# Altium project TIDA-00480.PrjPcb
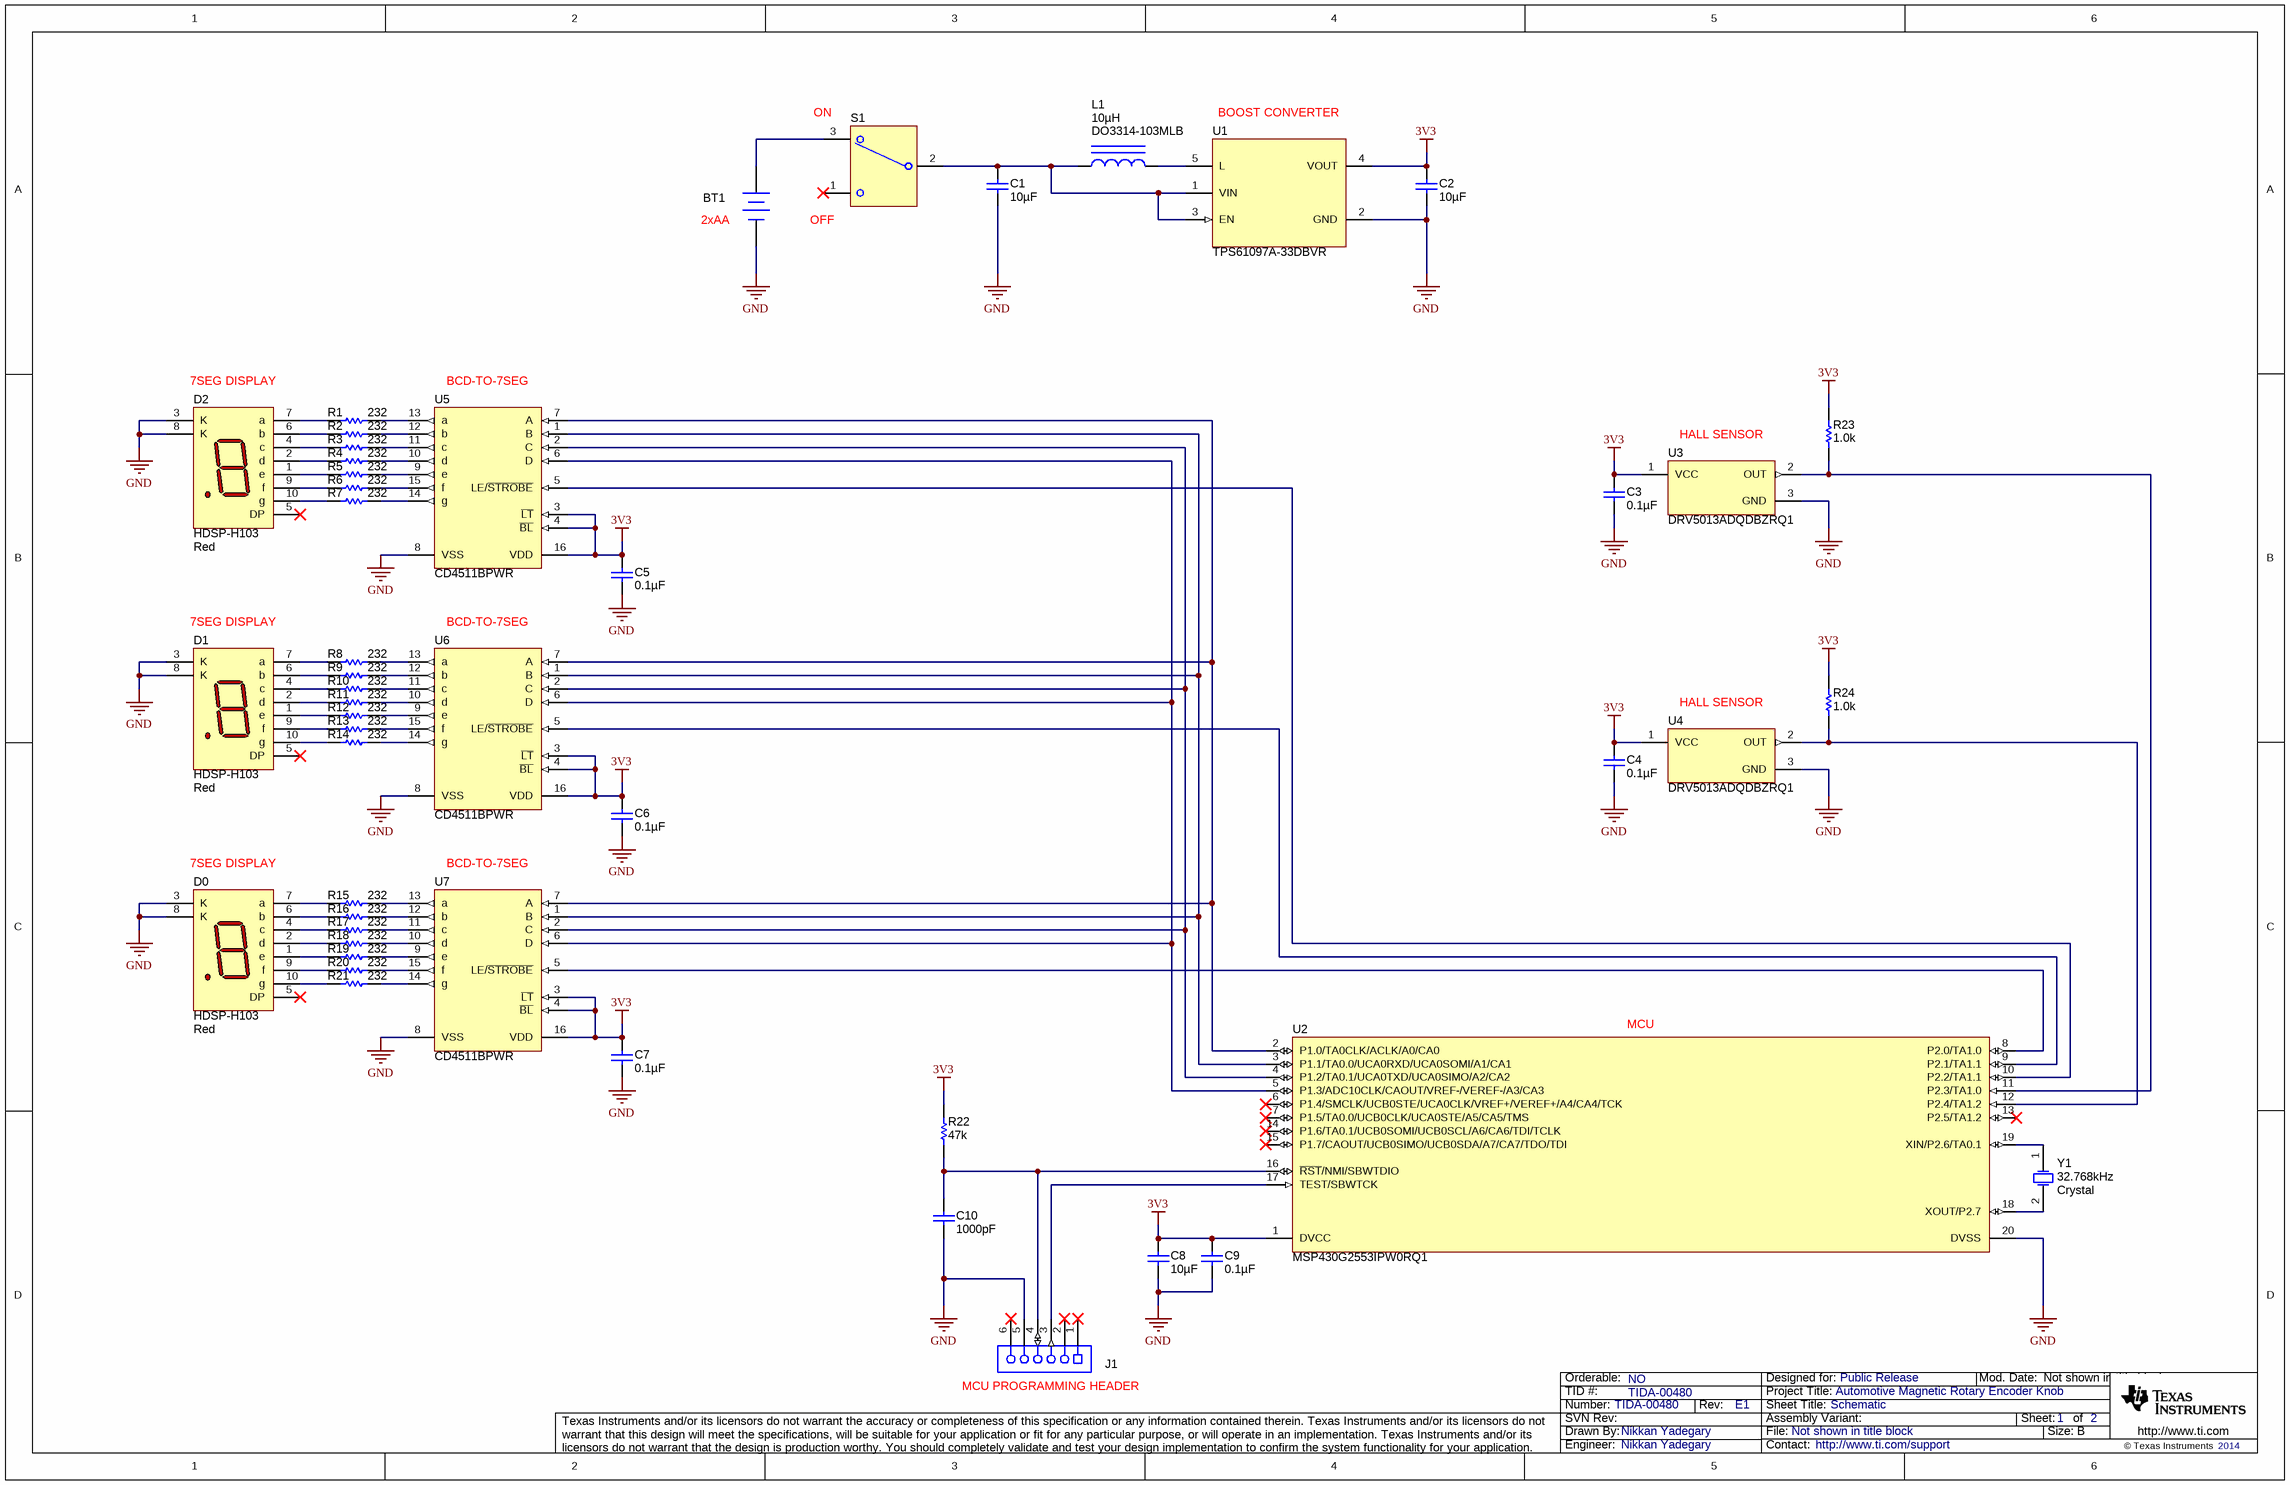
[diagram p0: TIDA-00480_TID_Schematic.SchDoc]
CopyrightYear: 2014; EVM_Orderable: NO; PCB_Rev: E1; PRJ_Customer: Public Release; PRJ_Engineer: Nikkan Yadegary; PRJ_Number: TIDA-00480; PRJ_Title: Automotive Magnetic Rotary Encoder Knob; SCH_Rev: E1; TechSupport: http://www.ti.com/support; TID: TIDA-00480
2 sheets, 68 parts. Net scope: global (net labels, ports and power ports of the same name join across sheets).
Board file: TIDA-00480_TID.PcbDoc
Sheets:
  TIDA-00480_TID_Schematic.SchDoc
  TIDA-00480_TID_Hardware.SchDoc

## Sheet TIDA-00480_TID_Schematic.SchDoc: Schematic
size 431 x 279 mm; Date: Not shown in title block; ApprovedBy: Not shown in title block; CheckedBy: Not shown in title block; Author: Not shown in title block; CompanyName: Not shown in title block; DrawnBy: Nikkan Yadegary; Engineer: Not shown in title block; Organization: Not shown in title block; Address1: Not shown in title block; Address2: Not shown in title block; Address3: Not shown in title block; Address4: Not shown in title block; DocumentNumber: 1; Revision: Use project parameter SCH_Rev; SheetNumber: 1; SheetTotal: 2; PageSetup: Record=PageOptions¦CenterHorizontal=True¦CenterVertical=True¦PrintScale=1.00¦XCorrection=1.00¦YCorrection=1.00¦PrintKind=0¦BorderSize=5000000¦LeftOffset=0¦BottomOffset=0¦Orientation=2¦PaperLength=1000¦PaperWidth=1000¦Scale=100¦PaperSource=15¦PrintQuality=600¦MediaType=1¦DitherType=10¦PaperKind=Letter¦PrintScaleMode=1

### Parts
BT1  2462  [Keystone_2462]  (value not drawn)
C1  ValueDisplayed: 10µF  [0603]  (hidden comment: GRM188R60J106ME47D)
C2  ValueDisplayed: 10µF  [0603]  (hidden comment: GRM188R60J106ME47D)
C3  ValueDisplayed: 0.1µF  [0402]  (hidden comment: GRM155R61A104KA01D)
C4  ValueDisplayed: 0.1µF  [0402]  (hidden comment: GRM155R61A104KA01D)
C5  ValueDisplayed: 0.1µF  [0402]  (hidden comment: GRM155R61A104KA01D)
C6  ValueDisplayed: 0.1µF  [0402]  (hidden comment: GRM155R61A104KA01D)
C7  ValueDisplayed: 0.1µF  [0402]  (hidden comment: GRM155R61A104KA01D)
C8  ValueDisplayed: 10µF  [0603]  (hidden comment: GRM188R60J106ME47D)
C9  ValueDisplayed: 0.1µF  [0402]  (hidden comment: GRM155R61A104KA01D)
C10  ValueDisplayed: 1000pF  [0402]  (hidden comment: GRM155R60J102KA01D)
D0  HDSP-H103  value Red  [HDSP_M_N_Red]
D1  HDSP-H103  value Red  [HDSP_M_N_Red]
D2  HDSP-H103  value Red  [HDSP_M_N_Red]
J1  851-43-006-20-001000  [CONN_851-43-006-20-001000]  (value not drawn)
L1  DO3314-103MLB  ValueDisplayed: 10µH  [DO3314]
R1  ValueDisplayed: 232  [0402]  (hidden comment: CRCW0402232RFKED)
R2  ValueDisplayed: 232  [0402]  (hidden comment: CRCW0402232RFKED)
R3  ValueDisplayed: 232  [0402]  (hidden comment: CRCW0402232RFKED)
R4  ValueDisplayed: 232  [0402]  (hidden comment: CRCW0402232RFKED)
R5  ValueDisplayed: 232  [0402]  (hidden comment: CRCW0402232RFKED)
R6  ValueDisplayed: 232  [0402]  (hidden comment: CRCW0402232RFKED)
R7  ValueDisplayed: 232  [0402]  (hidden comment: CRCW0402232RFKED)
R8  ValueDisplayed: 232  [0402]  (hidden comment: CRCW0402232RFKED)
R9  ValueDisplayed: 232  [0402]  (hidden comment: CRCW0402232RFKED)
R10  ValueDisplayed: 232  [0402]  (hidden comment: CRCW0402232RFKED)
R11  ValueDisplayed: 232  [0402]  (hidden comment: CRCW0402232RFKED)
R12  ValueDisplayed: 232  [0402]  (hidden comment: CRCW0402232RFKED)
R13  ValueDisplayed: 232  [0402]  (hidden comment: CRCW0402232RFKED)
R14  ValueDisplayed: 232  [0402]  (hidden comment: CRCW0402232RFKED)
R15  ValueDisplayed: 232  [0402]  (hidden comment: CRCW0402232RFKED)
R16  ValueDisplayed: 232  [0402]  (hidden comment: CRCW0402232RFKED)
R17  ValueDisplayed: 232  [0402]  (hidden comment: CRCW0402232RFKED)
R18  ValueDisplayed: 232  [0402]  (hidden comment: CRCW0402232RFKED)
R19  ValueDisplayed: 232  [0402]  (hidden comment: CRCW0402232RFKED)
R20  ValueDisplayed: 232  [0402]  (hidden comment: CRCW0402232RFKED)
R21  ValueDisplayed: 232  [0402]  (hidden comment: CRCW0402232RFKED)
R22  ValueDisplayed: 47k  [0402]  (hidden comment: CRCW040247K0JNED)
R23  ValueDisplayed: 1.0k  [0402]  (hidden comment: CRCW04021K00JNED)
R24  ValueDisplayed: 1.0k  [0402]  (hidden comment: CRCW04021K00JNED)
S1  500SSP1S2M2QEA  [SW_500SSP1S2M2xxA]  (value not drawn)
U1  TPS61097A-33DBVR  [DBV0005A_N]
U2  MSP430G2553IPW0RQ1  [PW0020A_N]
U3  DRV5013ADQDBZRQ1  [DBZ0003A_N]
U4  DRV5013ADQDBZRQ1  [DBZ0003A_N]
U5  CD4511BPWR  [PW0016A_N]
U6  CD4511BPWR  [PW0016A_N]
U7  CD4511BPWR  [PW0016A_N]
Y1  Frequency: 32.768kHz  CompType: Crystal  [XTAL_NX3215SA]  (hidden comment: NX3215SA-32.768K-STD-MUS-2)

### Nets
3V3: C2.1 C3.1 C4.1 C5.1 C6.1 C7.1 C8.1 C9.1 R22.2 R23.2 R24.2 U1.4(VOUT) U2.1(DVCC) U3.1(VCC) U4.1(VCC) U5.3(~{LT}) U5.4(~{BL}) U5.16(VDD) U6.3(~{LT}) U6.4(~{BL}) U6.16(VDD) U7.3(~{LT}) U7.4(~{BL}) U7.16(VDD)
GND: BT1.2(-) C1.2 C2.2 C3.2 C4.2 C5.2 C6.2 C7.2 C8.2 C9.2 C10.2 D0.3(K) D0.8(K) D1.3(K) D1.8(K) D2.3(K) D2.8(K) J1.5 U1.2(GND) U2.20(DVSS) U3.3(GND) U4.3(GND) U5.8(VSS) U6.8(VSS) U7.8(VSS)
NetBT1_1: BT1.1(+) S1.3
NetC1_1: C1.1 L1.1 S1.2(COM) U1.1(VIN) U1.3(EN)
NetC10_1: C10.1 J1.4 R22.1 U2.16(~{RST}/NMI/SBWTDIO)
NetD0_1: D0.1(e) R19.1
NetD0_2: D0.2(d) R18.1
NetD0_4: D0.4(c) R17.1
NetD0_6: D0.6(b) R16.1
NetD0_7: D0.7(a) R15.1
NetD0_9: D0.9(f) R20.1
NetD0_10: D0.10(g) R21.1
NetD1_1: D1.1(e) R12.1
NetD1_2: D1.2(d) R11.1
NetD1_4: D1.4(c) R10.1
NetD1_6: D1.6(b) R9.1
NetD1_7: D1.7(a) R8.1
NetD1_9: D1.9(f) R13.1
NetD1_10: D1.10(g) R14.1
NetD2_1: D2.1(e) R5.1
NetD2_2: D2.2(d) R4.1
NetD2_4: D2.4(c) R3.1
NetD2_6: D2.6(b) R2.1
NetD2_7: D2.7(a) R1.1
NetD2_9: D2.9(f) R6.1
NetD2_10: D2.10(g) R7.1
NetJ1_3: J1.3 U2.17(TEST/SBWTCK)
NetL1_2: L1.2 U1.5(L)
NetR1_2: R1.2 U5.13(a)
NetR2_2: R2.2 U5.12(b)
NetR3_2: R3.2 U5.11(c)
NetR4_2: R4.2 U5.10(d)
NetR5_2: R5.2 U5.9(e)
NetR6_2: R6.2 U5.15(f)
NetR7_2: R7.2 U5.14(g)
NetR8_2: R8.2 U6.13(a)
NetR9_2: R9.2 U6.12(b)
NetR10_2: R10.2 U6.11(c)
NetR11_2: R11.2 U6.10(d)
NetR12_2: R12.2 U6.9(e)
NetR13_2: R13.2 U6.15(f)
NetR14_2: R14.2 U6.14(g)
NetR15_2: R15.2 U7.13(a)
NetR16_2: R16.2 U7.12(b)
NetR17_2: R17.2 U7.11(c)
NetR18_2: R18.2 U7.10(d)
NetR19_2: R19.2 U7.9(e)
NetR20_2: R20.2 U7.15(f)
NetR21_2: R21.2 U7.14(g)
NetR23_1: R23.1 U2.11(P2.3/TA1.0) U3.2(OUT)
NetR24_1: R24.1 U2.12(P2.4/TA1.2) U4.2(OUT)
NetU2_2: U2.2(P1.0/TA0CLK/ACLK/A0/CA0) U5.7(A) U6.7(A) U7.7(A)
NetU2_3: U2.3(P1.1/TA0.0/UCA0RXD/UCA0SOMI/A1/CA1) U5.1(B) U6.1(B) U7.1(B)
NetU2_4: U2.4(P1.2/TA0.1/UCA0TXD/UCA0SIMO/A2/CA2) U5.2(C) U6.2(C) U7.2(C)
NetU2_5: U2.5(P1.3/ADC10CLK/CAOUT/VREF-/VEREF-/A3/CA3) U5.6(D) U6.6(D) U7.6(D)
NetU2_8: U2.8(P2.0/TA1.0) U7.5(LE/~{STROBE})
NetU2_9: U2.9(P2.1/TA1.1) U6.5(LE/~{STROBE})
NetU2_10: U2.10(P2.2/TA1.1) U5.5(LE/~{STROBE})
NetU2_18: U2.18(XOUT/P2.7) Y1.2(OSC2)
NetU2_19: U2.19(XIN/P2.6/TA0.1) Y1.1(OSC1)

Not connected (* = marked no-connect by the designer): D0 5(DP)*; D1 5(DP)*; D2 5(DP)*; J1 1* 2* 6*; S1 1*; U2 6(P1.4/SMCLK/UCB0STE/UCA0CLK/VREF+/VEREF+/A4/CA4/TCK)* 7(P1.5/TA0.0/UCB0CLK/UCA0STE/A5/CA5/TMS)* 13(P2.5/TA1.2)* 14(P1.6/TA0.1/UCB0SOMI/UCB0SCL/A6/CA6/TDI/TCLK)* 15(P1.7/CAOUT/UCB0SIMO/UCB0SDA/A7/CA7/TDO/TDI)*

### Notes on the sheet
- (near S1) ON
- (near U1) BOOST CONVERTER
- (near BT1) 2xAA
- (near S1) OFF
- (near D2) 7SEG DISPLAY
- (near U5) BCD-TO-7SEG
- (near U3) HALL SENSOR
- (near D1) 7SEG DISPLAY
- (near U6) BCD-TO-7SEG
- (near U4) HALL SENSOR
- (near D0) 7SEG DISPLAY
- (near U7) BCD-TO-7SEG
- (near U2) MCU
- (near J1) MCU PROGRAMMING HEADER

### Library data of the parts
BT1 = 2462: 2x AA Battery Holder, Through-hole mount; Manufacturer: Keystone
C1 C2 C8 = GRM188R60J106ME47D: CAP, CERM, 10 µF, 6.3 V, +/- 20%, X5R, 0603; Manufacturer: MuRata; Polarized: N; CompType: Capacitor; Value: 10uF; U/M: EA; Cap_F: 0.00001; Tolerance_%: 20; ESR_ohm: 0.009; Value1: 0.009 ohm; VDC_V: 6.3; Value2: 6.3V; IRMS_A: 2.74; TaMin_C: -55; TaMax_C: 125
C3-C7 C9 = GRM155R61A104KA01D: CAP, CERM, 0.1 µF, 10 V, +/- 10%, X5R, 0402; Manufacturer: MuRata; Polarized: N; CompType: Capacitor; Value: 0.1uF; U/M: EA; Cap_F: 0.0000001; Tolerance_%: 10; Value1: Unknown; Value2: 10V; TaMin_C: -55; TaMax_C: 85
C10 = GRM155R60J102KA01D: CAP, CERM, 1000 pF, 6.3 V, +/- 10%, X5R, 0402; Manufacturer: MuRata; Polarized: N; CompType: Capacitor; Value: 1000pF; U/M: EA; Cap_F: 0.000000001; Tolerance_%: 10; Value1: Unknown; VDC_V: 6.3; Value2: 6.3V; TaMin_C: -55; TaMax_C: 85
D0-D2 = HDSP-H103: LED, Red, TH; Manufacturer: Avago; SymbolCreator: Altium; Vf_V: 1.7; Value2: 1.7V; Io_A: 0.005; Vr_V: 15; Ir_A: 0.0001; Tjmax_C: 100; Value1: W; U/M: EA
J1 = 851-43-006-20-001000: Receptacle, 50mil, 6x1, Gold, R/A, TH; Manufacturer: Mill-Max; SymbolCreator: a0411947; U/M: EA
L1 = DO3314-103MLB: Inductor, Drum Core, Ferrite, 10 µH, 0.75 A, 0.52 ohm, SMD; Manufacturer: Coilcraft; Value: 10uH; Ind_H: 10.0E-6; Imax_A: 0.75; Irms: 0.75A @ 40C rise; Isat: 0.8A @ 10% inductance drop; DCR_ohm: 0.52; Value2: 0.75A
R1-R21 = CRCW0402232RFKED: RES, 232, 1%, 0.063 W, 0402; Manufacturer: Vishay-Dale; CompType: Resistor; Value: 232; Value_Code: 232R; Tolerance_%: 1; Power_W: 0.063; Value2: 0.063W; VDC_V: 50; TempCo: 100 ppm/C; EIA_Code: E96; U/M: EA
R22 = CRCW040247K0JNED: RES, 47 k, 5%, 0.063 W, 0402; Manufacturer: Vishay-Dale; CompType: Resistor; Value: 47k; Res_ohm: 47000; Value_Code: 47k0; Tolerance_%: 5; Power_W: 0.063; Value2: 0.063W; VDC_V: 50; TempCo: 200 ppm/C; EIA_Code: E24; U/M: EA
R23 R24 = CRCW04021K00JNED: RES, 1.0 k, 5%, 0.063 W, 0402; Manufacturer: Vishay-Dale; CompType: Resistor; Value: 1.0k; Res_ohm: 1000; Value_Code: 1k00; Tolerance_%: 5; Power_W: 0.063; Value2: 0.063W; VDC_V: 50; TempCo: 200 ppm/C; EIA_Code: E24; U/M: EA
S1 = 500SSP1S2M2QEA: Switch, SPDT, Slide, On-On, 2 Pos, TH; Manufacturer: E-Switch; SymbolCreator: x0208326; VDC_V: 28; PositionCount: 2; CurrentRating_mA: 5000
U1 = TPS61097A-33DBVR: Low-Input Voltage Synchronous-Boost Converter With Low Quiescent Current, DBV0005A; Alternate PartNumber: TPS61097A-33DBVT; Manufacturer: Texas Instruments; SymbolCreator: Altium; CompType: IC; U/M: EA
U2 = MSP430G2553IPW0RQ1: Automotive Mixed-Signal Microcontrollers, PW0020A; Manufacturer: Texas Instruments; SymbolCreator: Altium; CompType: IC; U/M: EA
U3 U4 = DRV5013ADQDBZRQ1: Automotive Digital-Latch Hall Effect Sensor, DBZ0003A; Alternate PartNumber: DRV5013ADQDBZTQ1; Manufacturer: Texas Instruments; SymbolCreator: a0799628; CompType: IC; U/M: EA
U5-U7 = CD4511BPWR: CMOS BCD-to-7-Segment LED Latch / Decoder / Driver, 3 to 18 V, -55 to 125 degC, 16-pin SOP (PW16), Green (RoHS & no Sb/Br); Manufacturer: Texas Instruments; Alternate Manufacturer: None; Alternate PartNumber: Equivalent; Rating: Military; SubFamily: Discrete Segment LED Driver; Vin(Max)(V): 18; Vin(Min)(V): 3
Y1 = NX3215SA-32.768K-STD-MUS-2: Crystal, 32.768kHz, 12.5pF, SMD; Manufacturer: NDK; SymbolCreator: a0412235; U/M: EA; TaMin_C: -40; TaMax_C: 125; Frequency Stability: ±20ppm

## Sheet TIDA-00480_TID_Hardware.SchDoc: Hardware
size 431 x 279 mm; Date: Not shown in title block; ApprovedBy: Not shown in title block; CheckedBy: Not shown in title block; Author: Not shown in title block; CompanyName: Not shown in title block; DrawnBy: Nikkan Yadegary; Engineer: Not shown in title block; Organization: Not shown in title block; Address1: Not shown in title block; Address2: Not shown in title block; Address3: Not shown in title block; Address4: Not shown in title block; DocumentNumber: 2; Revision: Use project parameter SCH_Rev; SheetNumber: 2; SheetTotal: 2; PageSetup: Record=PageOptions¦CenterHorizontal=True¦CenterVertical=True¦PrintScale=1.00¦XCorrection=1.00¦YCorrection=1.00¦PrintKind=0¦BorderSize=5000000¦LeftOffset=0¦BottomOffset=0¦Orientation=2¦PaperLength=1000¦PaperWidth=1000¦Scale=100¦PaperSource=15¦PrintQuality=600¦MediaType=1¦DitherType=10¦PaperKind=Letter¦PrintScaleMode=1
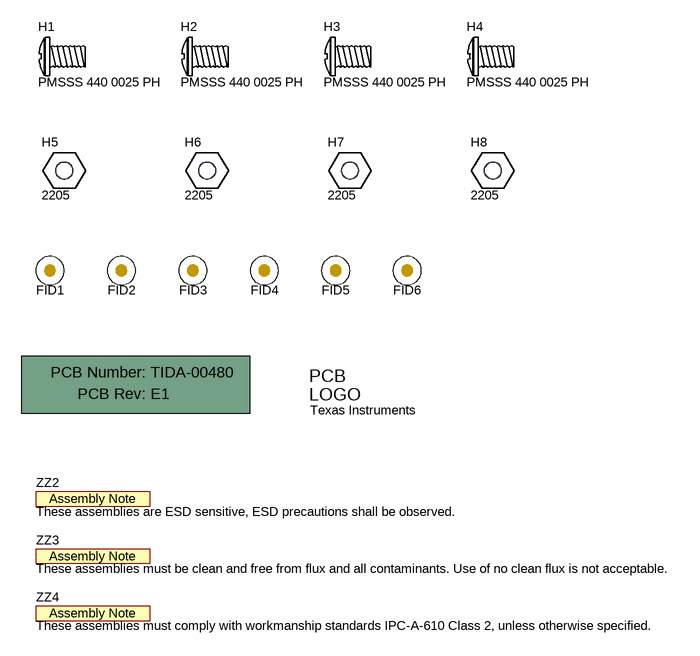
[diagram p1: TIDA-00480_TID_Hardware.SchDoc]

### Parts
!PCB  Printed Circuit Board  (value not drawn)  (mechanical)
FID1  Fiducial  [Fiducial10-20]  (value not drawn)
FID2  Fiducial  [Fiducial10-20]  (value not drawn)
FID3  Fiducial  [Fiducial10-20]  (value not drawn)
FID4  Fiducial  [Fiducial10-20]  (value not drawn)
FID5  Fiducial  [Fiducial10-20]  (value not drawn)
FID6  Fiducial  [Fiducial10-20]  (value not drawn)
H1  PMSSS 440 0025 PH  (mechanical)
H2  PMSSS 440 0025 PH  (mechanical)
H3  PMSSS 440 0025 PH  (mechanical)
H4  PMSSS 440 0025 PH  (mechanical)
H5  2205  [KEYSTONE_2205]
H6  2205  [KEYSTONE_2205]
H7  2205  [KEYSTONE_2205]
H8  2205  [KEYSTONE_2205]
Logo1  Texas Instruments  [TI_Horizontal_SolderMask_Medium]  (no BOM)
ZZ2  These assemblies are ESD sensitive, ESD precautions shall be observed.  [AssemblyNote]  (no BOM)
ZZ3  These assemblies must be clean and free from flux and all contaminants. Use of no clean flux is not acceptable.  [AssemblyNote]  (no BOM)
ZZ4  These assemblies must comply with workmanship standards IPC-A-610 Class 2, unless otherwise specified.  [AssemblyNote]  (no BOM)

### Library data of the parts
!PCB = PCB: Manufacturer: Any; PartNumber: TIDA-00480; SymbolCreator: a0412235
FID1-FID6 = Fiducial: Fiducial mark.  There is nothing to buy or mount.; SymbolCreator: codlsc
H1-H4 = PMSSS 440 0025 PH: MACHINE SCREW PAN PHILLIPS 4-40; Manufacturer: B&F Fastener Supply; SymbolCreator: a0412235; CompType: Standoff
H5-H8 = 2205: Standoff, Hex, 1"L #4-40 Aluminum; Manufacturer: Keystone; SymbolCreator: a0412235
Logo1 = TI_Logo: Texas Instrument Corporate Signature; SymbolCreator: codlsc
ZZ2-ZZ4 = AssemblyNote: SymbolCreator: codlsc

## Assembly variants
001: not fitted FID1 FID2 FID3 FID4 FID5 FID6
